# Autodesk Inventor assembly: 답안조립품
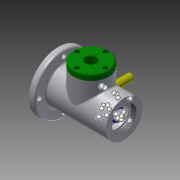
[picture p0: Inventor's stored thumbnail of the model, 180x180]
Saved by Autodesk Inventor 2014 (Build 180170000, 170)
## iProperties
Created: 2016-08
Part Number: 답안조립품
Document SubType Name: Assembly
Designer: owner
Author: owner
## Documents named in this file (15)
- C:\Users\owner\Desktop\460807V1006\답안조립품.iam
- C:\Users\owner\Desktop\460807V1006\본체.ipt
- C:\Users\owner\Desktop\460807V1006\베어링 15 x 35 x 11.ipt
- C:\Users\owner\Desktop\460807V1006\부시1.ipt
- C:\Users\owner\Desktop\460807V1006\편심축.ipt
- C:\Users\owner\Desktop\460807V1006\멈춤링 35x1.6.ipt
- C:\Users\owner\Desktop\460807V1006\링크.ipt
- C:\Users\owner\Desktop\460807V1006\슬라이더.ipt
- C:\Users\owner\Desktop\460807V1006\클래스터 핀 6 x 24.ipt
- C:\Users\owner\Desktop\460807V1006\부시2.ipt
- C:\Users\owner\Desktop\460807V1006\와셔 10x21.ipt
- C:\Users\owner\Desktop\460807V1006\너트 M10.ipt
- C:\Users\owner\Desktop\460807V1006\멈춤링 15 x 1.ipt
- C:\Users\owner\Desktop\460807V1006\탑 커버.ipt
- 탑 커버.ipt
